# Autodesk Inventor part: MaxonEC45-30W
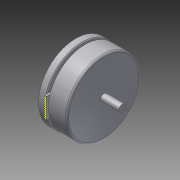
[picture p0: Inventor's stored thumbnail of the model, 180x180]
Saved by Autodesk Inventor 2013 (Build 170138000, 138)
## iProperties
Created: 2012-07
Part Number: MaxonEC45-30W
Material: Aluminium 6061
Document SubType Name: Modeling
Designer: rYan
Density: 2.71 g/cm^3
Mass: 62.7242 g
Surface Area: 80.7441 cm^2
Volume: 23.1455 cm^3
Categories: <MemberInstance><Categories><Category DisplayName="" Mnemonic="CABLEANDHARNESS" InternalName="e4a7e005-5e42-4d16-b293-125e7f0d0512"><Category DisplayName="" Mne
GlobalPropertyList: <PropertyList/>
Author: rYan
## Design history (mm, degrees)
sketch "Skizze1"
  geometry: L1 (-3.2, 2)-(-3.2, 6); L2 (-3.2, 6)-(0, 6); L3 (0, 6)-(0, 21.6); L4 (16.4, 21.35)-(16.4, 2); L5 (-10, 0)-(27, 0); L6 (-17.4, 0)-(34.4, 0) reference; L7 (0, 21.6)-(4, 21.6); L8 (4, 21.6)-(4, 18.6); L9 (4, 18.6)-(5.5, 18.6); L10 (5.5, 18.6)-(5.5, 21.35); L11 (5.5, 21.35)-(16.4, 21.35); L12 (-3.2, 2)-(-10, 2); L13 (-10, 2)-(-10, 0); L14 (16.4, 2)-(27, 2); L15 (27, 2)-(27, 0); 1 further point
  constraints: 28 end point, 6 parallel, 6 perpendicular, 3 point on line, 1 collinear, 1 vertical
  dimensions: "d2" = 12 diameter of L2 L5; "d5" = 3.2 distance between parallel lines of L1 L3; "d6" = 16.4 distance between parallel lines of L4 L3; "d7" = 4 distance between parallel lines of L3 L8; "d8" = 1.5 distance between parallel lines of L10 L8; "d9" = 43.2 diameter of L7 L5; "d10" = 42.7 diameter of L11 L5; "d11" = 3 distance between parallel lines of L9 L7; "d44" = 10 distance between parallel lines of L3 L13; "d45" = 4 diameter of L12 L5; "d46" = 27 distance between parallel lines of L15 L3; "d47" = 4 diameter of L14 L5
revolve "Umdrehung1" sketch "Skizze1" stored, may be unused: angle "d12" = 90 deg
fillet "Rundung1" dims "d13" = 1
chamfer "Fase1" distance "d14" = 0.5; stored, may be unused: second distance "d15" = 2, angle "d16" = 45 deg
sketch "Skizze2"
  geometry: C1 r 6 at (0, 0) reference; C2 r 5 at (0, 0); C3 r 2 at (0, 0) reference; C4 r 2 at (0, 0); 1 further point
  constraints: 2 centre point, 2 coincident, 1 concentric
  dimensions: "d17" = 1 radial gap between concentric circles of C1 C2
extrude "Extrusion3" cut sketch "Skizze2" distance "d48" = 1; taper "d49" = 0 deg
sketch "Skizze4" dims "d27" = 22
  geometry: L1 (0, 30.32)-(0, -30.72) reference; 3 further points
  constraints: 1 coincident, 1 point on line, 1 vertical alignment, 2 other
hole "Bohrung2" sketch "Skizze4" at (0, 11) diameter "d29" = 2.459; stored, may be unused: countersink angle "d33" = 82 deg, drill point angle "d35" = 118 deg; dims "d30" = 6, "d31" = 3.023, "d32" = 2, "d34" = 3.9
pattern_circular "Runde Anordnung2" dims angle "d51" = 360 deg
sketch "Skizze5"
  geometry: L1 (0, -30.72)-(0, 30.32) reference; L2 (-6, -17.606)-(-6, -22); L3 (-6, -22)-(6, -22); L4 (6, -22)-(6, -17.606); A1 r 18.6 centre (0, 0) between (-6, -17.606) and (6, -17.606) reference; A2 r 18.6 centre (0, 0) between (-6, -17.606) and (6, -17.606); 1 further point
  constraints: 6 end point, 4 point on circle, 2 parallel, 1 centre point, 1 coincident, 1 perpendicular, 1 other
  dimensions: "d39" = 22 distance from line of L3 point (0, 0); "d40" = 12 distance of L2.end L3.end
extrude "Extrusion2" join sketch "Skizze5" distance "d41" = 1; taper "d42" = 0 deg
sketch "Skizze6"
  geometry: L1 (0, 12)-(0, 0) reference; L2 (0, 0)-(1, 0) reference; L3 (1, 12)-(1, 0) reference; L4 (0, 12)-(1, 12) reference; L5 (0.5, 12)-(0.5, 0); L6 (0, 6)-(1, 6); 3 further points
  constraints: 5 midpoint, 4 end point, 1 point on line
  dimensions: "d43" = 1 distance from line of L2 point (0.5, 1)
  node "Projizierte Kontur1"
node "1"
node "2"
node "3"
node "4"
node "5"
node "6"
node "7"
node "8"
node "9"
node "10"
node "11"
node "Volumenkörper1"
